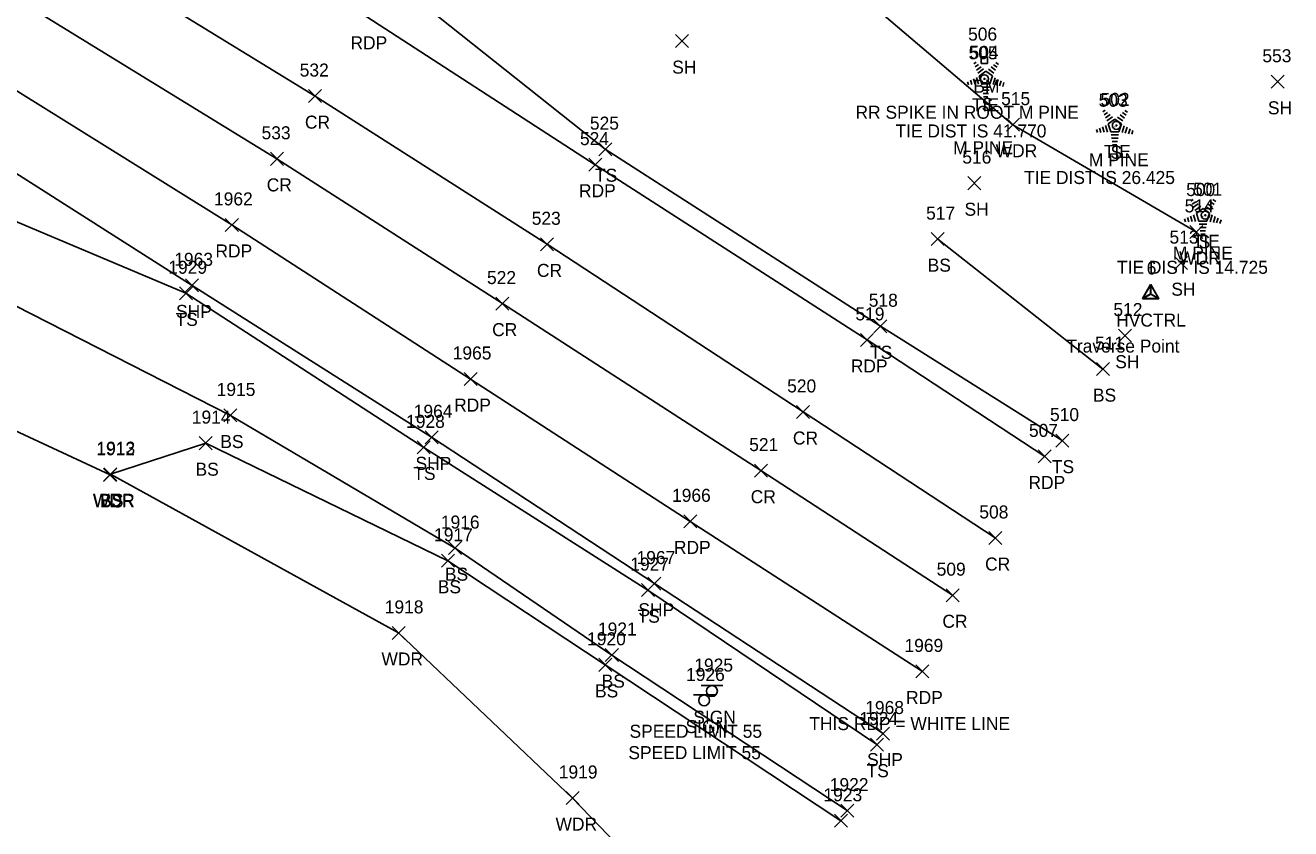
# Model space of a CAD drawing. Extents: x 1629176 to 1637209, y 606063 to 610167.
# Drawn here: x 1630613 to 1630807.4, y 606523.7 to 606647 of the extents above; entities that cross this region are included whole.
import ezdxf

# ---------------------------------------------------------------- set-up
doc = ezdxf.new("R2010")
doc.units = 0
for name, color, linetype in [('C_A', 7, 'Continuous'), ('C_C', 7, 'Continuous'), ('C_I', 7, 'Continuous'), ('CBP', 7, 'Continuous'), ('CPBM', 7, 'Continuous'), ('CPSM', 7, 'Continuous'), ('L_A', 7, 'Continuous'), ('L_C', 7, 'Continuous'), ('L_I', 7, 'Continuous'), ('L_TIC', 7, 'Continuous'), ('LAWA', 7, 'Continuous'), ('LELB', 7, 'Continuous'), ('LTC', 7, 'Continuous'), ('P_A', 7, 'Continuous'), ('P_C', 7, 'Continuous'), ('P_I', 7, 'Continuous'), ('P_TIC', 7, 'Continuous'), ('PET', 7, 'Continuous'), ('PRC', 7, 'Continuous'), ('PSP', 7, 'Continuous'), ('S_A', 7, 'Continuous'), ('S_C', 7, 'Continuous'), ('S_I', 7, 'Continuous'), ('SSGN', 7, 'Continuous')]:
    doc.layers.add(name, color=color, linetype=linetype)

msp = doc.modelspace()

# ---------------------------------------------------------------- linework, layer by layer
at = {"layer": 'CBP'}
for centre, radius in [((1630760.34, 606638.81), 0.625), ((1630760.34, 606638.81), 0.0833), ((1630780.62, 606631.66), 0.625), ((1630780.62, 606631.66), 0.0833), ((1630794.28, 606617.87), 0.625), ((1630794.28, 606617.87), 0.0833)]:
    msp.add_circle(centre, radius, dxfattribs=at)
at = {"layer": 'CPBM'}
for p, q in [((1630759.82, 606641.18), (1630759.82, 606642.18)), ((1630759.82, 606642.18), (1630760.82, 606642.18)), ((1630760.82, 606641.18), (1630759.82, 606641.18)), ((1630760.33, 606641.68), (1630760.33, 606641.68)), ((1630760.33, 606641.68), (1630760.33, 606641.68)), ((1630760.82, 606642.18), (1630760.82, 606641.18))]:
    msp.add_line(p, q, dxfattribs=at)
at = {"layer": 'CPSM'}
for p, q in [((1630784.62, 606605.06), (1630785.87, 606607.23)), ((1630784.64, 606605.05), (1630785.89, 606607.21)), ((1630787.12, 606605.06), (1630785.87, 606607.23)), ((1630785.87, 606605.78), (1630785.87, 606607.23)), ((1630787.14, 606605.05), (1630785.89, 606607.21)), ((1630785.89, 606605.77), (1630785.89, 606607.21)), ((1630784.62, 606605.06), (1630785.87, 606605.78)), ((1630784.62, 606605.06), (1630787.12, 606605.06)), ((1630784.64, 606605.05), (1630785.89, 606605.77)), ((1630784.64, 606605.05), (1630787.14, 606605.05)), ((1630785.87, 606605.78), (1630785.87, 606605.78)), ((1630785.87, 606605.78), (1630787.12, 606605.06)), ((1630785.89, 606605.77), (1630785.89, 606605.77)), ((1630785.89, 606605.77), (1630787.14, 606605.05))]:
    msp.add_line(p, q, dxfattribs=at)
at = {"layer": 'L_TIC'}
for points in [[(1630712.88, 606643.61), (1630714.88, 606645.61)], [(1630714.88, 606643.61), (1630712.88, 606645.61)], [(1630804.42, 606637.36), (1630806.42, 606639.36)], [(1630806.42, 606637.36), (1630804.42, 606639.36)], [(1630763.71, 606630.77), (1630765.71, 606632.77)], [(1630765.71, 606630.77), (1630763.71, 606632.77)], [(1630701.09, 606627.01), (1630703.09, 606629.01)], [(1630703.09, 606627.01), (1630701.09, 606629.01)], [(1630757.79, 606621.79), (1630759.79, 606623.79)], [(1630759.79, 606621.79), (1630757.79, 606623.79)], [(1630791.9, 606614.3), (1630793.9, 606616.3)], [(1630793.9, 606614.3), (1630791.9, 606616.3)], [(1630752.18, 606613.2), (1630754.18, 606615.2)], [(1630754.18, 606613.2), (1630752.18, 606615.2)], [(1630789.57, 606609.51), (1630791.57, 606611.51)], [(1630791.57, 606609.51), (1630789.57, 606611.51)], [(1630636.64, 606604.88), (1630638.64, 606606.88)], [(1630638.64, 606604.88), (1630636.64, 606606.88)], [(1630743.36, 606599.82), (1630745.36, 606601.82)], [(1630745.36, 606599.82), (1630743.36, 606601.82)], [(1630780.96, 606598.38), (1630782.96, 606600.38)], [(1630782.96, 606598.38), (1630780.96, 606600.38)], [(1630777.56, 606593.24), (1630779.56, 606595.24)], [(1630779.56, 606593.24), (1630777.56, 606595.24)], [(1630643.49, 606586.12), (1630645.49, 606588.12)], [(1630645.49, 606586.12), (1630643.49, 606588.12)], [(1630639.68, 606581.87), (1630641.68, 606583.87)], [(1630641.68, 606581.87), (1630639.68, 606583.87)], [(1630673.18, 606581.22), (1630675.18, 606583.22)], [(1630675.18, 606581.22), (1630673.18, 606583.22)], [(1630771.3, 606582.26), (1630773.3, 606584.26)], [(1630773.3, 606582.26), (1630771.3, 606584.26)], [(1630625, 606577), (1630627, 606579)], [(1630627, 606577), (1630625, 606579)], [(1630625, 606577), (1630627, 606579)], [(1630627, 606577), (1630625, 606579)], [(1630625.04, 606577.1), (1630627.04, 606579.1)], [(1630627.04, 606577.1), (1630625.04, 606579.1)], [(1630625.04, 606577.1), (1630627.04, 606579.1)], [(1630627.04, 606577.1), (1630625.04, 606579.1)], [(1630678, 606565.75), (1630680, 606567.75)], [(1630680, 606565.75), (1630678, 606567.75)], [(1630676.91, 606563.81), (1630678.91, 606565.81)], [(1630678.91, 606563.81), (1630676.91, 606565.81)], [(1630707.63, 606559.3), (1630709.63, 606561.3)], [(1630709.63, 606559.3), (1630707.63, 606561.3)], [(1630669.33, 606552.73), (1630671.33, 606554.73)], [(1630671.33, 606552.73), (1630669.33, 606554.73)], [(1630701.07, 606547.83), (1630703.07, 606549.83)], [(1630703.07, 606547.83), (1630701.07, 606549.83)], [(1630702.09, 606549.33), (1630704.09, 606551.33)], [(1630704.09, 606549.33), (1630702.09, 606551.33)], [(1630742.82, 606535.58), (1630744.82, 606537.58)], [(1630744.82, 606535.58), (1630742.82, 606537.58)], [(1630696.07, 606527.38), (1630698.07, 606529.38)], [(1630698.07, 606527.38), (1630696.07, 606529.38)], [(1630738.27, 606525.44), (1630740.27, 606527.44)], [(1630740.27, 606525.44), (1630738.27, 606527.44)], [(1630737.3, 606523.88), (1630739.3, 606525.88)], [(1630739.3, 606523.88), (1630737.3, 606525.88)]]:
    msp.add_lwpolyline(points, dxfattribs=at)
at = {"layer": 'LAWA'}
for points in [[(1630792.9, 606615.3), (1630764.71, 606631.77), (1630727.23, 606663.62), (1630696.05, 606688.29), (1630643.61, 606720.78), (1630609.4, 606762.16), (1630595.94, 606778.67), (1630581.31, 606798.55), (1630556.61, 606821.27), (1630561.53, 606852.75)], [(1630297.68, 606682.91), (1630335.71, 606675.48), (1630386.4, 606666.36), (1630422.65, 606653.68), (1630444.38, 606639.08), (1630446.66, 606637.81), (1630486.16, 606613.28), (1630514.89, 606608.05), (1630539.89, 606609.62), (1630562.09, 606603.08), (1630591.48, 606594.03), (1630626, 606578), (1630626.04, 606578.1), (1630670.33, 606553.73), (1630697.07, 606528.38), (1630722.88, 606501.58)]]:
    msp.add_lwpolyline(points, dxfattribs=at)
at = {"layer": 'LELB'}
for points in [[(1630772.3, 606583.26), (1630744.36, 606600.82), (1630702.09, 606628.01), (1630669.73, 606653.69), (1630639.16, 606677.6), (1630625.62, 606682.65), (1630575.5, 606708.79), (1630543.73, 606726.11), (1630517.88, 606742.14), (1630478.23, 606762.96), (1630430.43, 606788.65), (1630392.8, 606806.98), (1630357.66, 606823.31), (1630317.9, 606842.29), (1630273.51, 606862.27), (1630239.69, 606876.29), (1630209.67, 606888.82), (1630166.54, 606905.65), (1630125.1, 606921.22), (1630084.2, 606935.53), (1630049.16, 606947.36)], [(1630743.82, 606536.58), (1630708.63, 606560.3), (1630674.18, 606582.22), (1630637.64, 606605.88), (1630594.34, 606624.1), (1630571.59, 606644.34), (1630541.22, 606663.48), (1630507.65, 606682.45), (1630477.7, 606699.4), (1630450.89, 606713.6)], [(1630469.72, 606651.64), (1630496.75, 606635.89), (1630520.54, 606626.59), (1630540.08, 606622.19), (1630567.61, 606620.59), (1630601.15, 606609.16), (1630644.49, 606587.12), (1630679, 606566.75), (1630703.09, 606550.33), (1630739.27, 606526.44)], [(1630778.56, 606594.24), (1630753.18, 606614.2)], [(1630626.04, 606578.1), (1630640.68, 606582.87), (1630677.91, 606564.81), (1630702.07, 606548.83), (1630738.3, 606524.88)]]:
    msp.add_lwpolyline(points, dxfattribs=at)
at = {"layer": 'LTC'}
for p, q in [((1630758.7, 606641.09), (1630759.05, 606641.35)), ((1630762.1, 606641.33), (1630762.52, 606641.03)), ((1630758.91, 606640.63), (1630759.44, 606641.01)), ((1630759.12, 606640.16), (1630759.82, 606640.67)), ((1630759.33, 606639.7), (1630760.21, 606640.33)), ((1630759.55, 606639.24), (1630760.56, 606639.97)), ((1630759.55, 606639.24), (1630759.94, 606638.05)), ((1630760.56, 606639.97), (1630761.56, 606639.25)), ((1630760.98, 606640.29), (1630761.79, 606639.7)), ((1630761.56, 606639.25), (1630761.17, 606638.05)), ((1630761.36, 606640.64), (1630762.03, 606640.14)), ((1630761.73, 606640.98), (1630762.28, 606640.59)), ((1630757.73, 606638.37), (1630757.88, 606637.9)), ((1630758.19, 606638.59), (1630758.4, 606637.94)), ((1630758.64, 606638.8), (1630758.91, 606637.97)), ((1630759.1, 606639.02), (1630759.43, 606638)), ((1630761.17, 606638.05), (1630759.94, 606638.05)), ((1630761.13, 606637.55), (1630759.99, 606637.55)), ((1630762, 606638.98), (1630761.66, 606637.94)), ((1630762.44, 606638.73), (1630762.16, 606637.84)), ((1630762.89, 606638.48), (1630762.65, 606637.75)), ((1630763.33, 606638.23), (1630763.15, 606637.65)), ((1630761.05, 606637.05), (1630760.06, 606637.05)), ((1630760.96, 606636.55), (1630760.13, 606636.55)), ((1630760.88, 606636.05), (1630760.21, 606636.05)), ((1630778.53, 606633.73), (1630778.88, 606633.99)), ((1630778.74, 606633.27), (1630779.27, 606633.65)), ((1630778.95, 606632.8), (1630779.65, 606633.31)), ((1630781.19, 606633.28), (1630781.86, 606632.78)), ((1630781.56, 606633.63), (1630782.11, 606633.23)), ((1630781.93, 606633.97), (1630782.35, 606633.67)), ((1630778.47, 606631.45), (1630778.74, 606630.61)), ((1630778.93, 606631.66), (1630779.26, 606630.64)), ((1630779.16, 606632.34), (1630780.04, 606632.97)), ((1630779.38, 606631.88), (1630780.39, 606632.62)), ((1630779.38, 606631.88), (1630779.77, 606630.69)), ((1630780.39, 606632.62), (1630781.39, 606631.89)), ((1630780.81, 606632.93), (1630781.62, 606632.34)), ((1630781.39, 606631.89), (1630781, 606630.69)), ((1630781.83, 606631.62), (1630781.49, 606630.58)), ((1630782.27, 606631.37), (1630781.99, 606630.49)), ((1630777.56, 606631.01), (1630777.71, 606630.55)), ((1630778.02, 606631.23), (1630778.23, 606630.58)), ((1630781, 606630.69), (1630779.77, 606630.69)), ((1630780.96, 606630.19), (1630779.82, 606630.19)), ((1630780.88, 606629.69), (1630779.89, 606629.69)), ((1630782.72, 606631.12), (1630782.48, 606630.39)), ((1630783.16, 606630.87), (1630782.98, 606630.3)), ((1630780.79, 606629.19), (1630779.96, 606629.19)), ((1630780.71, 606628.69), (1630780.04, 606628.69)), ((1630792.06, 606620.02), (1630792.42, 606620.28)), ((1630792.27, 606619.56), (1630792.8, 606619.94)), ((1630795.09, 606619.91), (1630795.64, 606619.51)), ((1630795.46, 606620.26), (1630795.88, 606619.96)), ((1630792.01, 606617.73), (1630792.28, 606616.9)), ((1630792.46, 606617.95), (1630792.79, 606616.93)), ((1630792.48, 606619.09), (1630793.19, 606619.6)), ((1630792.69, 606618.62), (1630793.57, 606619.26)), ((1630792.92, 606618.17), (1630793.93, 606618.9)), ((1630792.92, 606618.17), (1630793.3, 606616.98)), ((1630793.93, 606618.9), (1630794.93, 606618.18)), ((1630794.35, 606619.22), (1630795.16, 606618.63)), ((1630794.93, 606618.18), (1630794.53, 606616.98)), ((1630794.72, 606619.57), (1630795.4, 606619.07)), ((1630795.36, 606617.91), (1630795.02, 606616.87)), ((1630791.1, 606617.3), (1630791.25, 606616.83)), ((1630791.55, 606617.52), (1630791.76, 606616.87)), ((1630794.53, 606616.98), (1630793.3, 606616.98)), ((1630794.5, 606616.48), (1630793.35, 606616.48)), ((1630794.41, 606615.98), (1630793.42, 606615.98)), ((1630795.81, 606617.66), (1630795.52, 606616.77)), ((1630796.25, 606617.41), (1630796.01, 606616.68)), ((1630796.7, 606617.16), (1630796.51, 606616.58)), ((1630794.33, 606615.48), (1630793.5, 606615.48)), ((1630794.24, 606614.98), (1630793.57, 606614.98))]:
    msp.add_line(p, q, dxfattribs=at)
at = {"layer": 'P_TIC'}
for points in [[(1630656.5, 606635.16), (1630658.5, 606637.16)], [(1630658.5, 606635.16), (1630656.5, 606637.16)], [(1630650.63, 606625.53), (1630652.63, 606627.53)], [(1630652.63, 606625.53), (1630650.63, 606627.53)], [(1630699.55, 606624.63), (1630701.55, 606626.63)], [(1630701.55, 606624.63), (1630699.55, 606626.63)], [(1630643.7, 606615.38), (1630645.7, 606617.38)], [(1630645.7, 606615.38), (1630643.7, 606617.38)], [(1630692.14, 606612.4), (1630694.14, 606614.4)], [(1630694.14, 606612.4), (1630692.14, 606614.4)], [(1630637.6, 606606.1), (1630639.6, 606608.1)], [(1630639.6, 606606.1), (1630637.6, 606608.1)], [(1630685.27, 606603.3), (1630687.27, 606605.3)], [(1630687.27, 606603.3), (1630685.27, 606605.3)], [(1630741.32, 606597.72), (1630743.32, 606599.72)], [(1630743.32, 606597.72), (1630741.32, 606599.72)], [(1630680.38, 606591.72), (1630682.38, 606593.72)], [(1630682.38, 606591.72), (1630680.38, 606593.72)], [(1630731.48, 606586.66), (1630733.48, 606588.66)], [(1630733.48, 606586.66), (1630731.48, 606588.66)], [(1630674.39, 606582.77), (1630676.39, 606584.77)], [(1630676.39, 606582.77), (1630674.39, 606584.77)], [(1630768.62, 606579.83), (1630770.62, 606581.83)], [(1630770.62, 606579.83), (1630768.62, 606581.83)], [(1630725, 606577.65), (1630727, 606579.65)], [(1630727, 606577.65), (1630725, 606579.65)], [(1630714.14, 606569.86), (1630716.14, 606571.86)], [(1630716.14, 606569.86), (1630714.14, 606571.86)], [(1630761, 606567.31), (1630763, 606569.31)], [(1630763, 606567.31), (1630761, 606569.31)], [(1630708.63, 606560.3), (1630710.63, 606562.3)], [(1630710.63, 606560.3), (1630708.63, 606562.3)], [(1630754.45, 606558.52), (1630756.45, 606560.52)], [(1630756.45, 606558.52), (1630754.45, 606560.52)], [(1630749.81, 606546.81), (1630751.81, 606548.81)], [(1630751.81, 606546.81), (1630749.81, 606548.81)], [(1630743.78, 606537.28), (1630745.78, 606539.28)], [(1630745.78, 606537.28), (1630743.78, 606539.28)]]:
    msp.add_lwpolyline(points, dxfattribs=at)
at = {"layer": 'PET'}
for points in [[(1630769.62, 606580.83), (1630742.32, 606598.72), (1630700.55, 606625.63), (1630665.45, 606648.34), (1630621.98, 606674.98), (1630606.18, 606684.39), (1630572.37, 606704.1), (1630541.12, 606722.17), (1630498.96, 606745.43), (1630457.51, 606767.81), (1630420.78, 606786.67), (1630374.62, 606809.25), (1630335.12, 606827.65), (1630289.38, 606848.42), (1630250.13, 606865.31), (1630203.69, 606884.49), (1630159.86, 606901.83), (1630115.59, 606918.47), (1630070.26, 606934.37)], [(1630050.76, 606901.68), (1630096.23, 606885.67), (1630143.35, 606868.08), (1630186.15, 606851.44), (1630235.05, 606831.31), (1630271.1, 606815.81), (1630310.69, 606798.07), (1630353.79, 606777.93), (1630392.73, 606758.86), (1630432.29, 606738.62), (1630464.02, 606722.09), (1630502.44, 606701.07), (1630537.98, 606680.83), (1630570.03, 606662.27), (1630609.11, 606638.58), (1630644.7, 606616.38), (1630681.38, 606592.72), (1630715.14, 606570.86), (1630750.81, 606547.81)]]:
    msp.add_lwpolyline(points, dxfattribs=at)
at = {"layer": 'PRC'}
for points in [[(1630762, 606568.31), (1630732.48, 606587.66), (1630693.14, 606613.4), (1630657.5, 606636.16), (1630615.44, 606661.97), (1630565.18, 606692.12), (1630533.4, 606710.56), (1630491.42, 606733.47), (1630450.45, 606755.19), (1630412.78, 606774.87), (1630369.5, 606796.13), (1630328.6, 606815.23), (1630283.03, 606835.75), (1630244.34, 606852.21), (1630197.18, 606871.73), (1630154.28, 606888.46), (1630110.18, 606905.77), (1630065.36, 606921.68)], [(1630755.45, 606559.52), (1630726, 606578.65), (1630686.27, 606604.3), (1630651.63, 606626.53), (1630610.5, 606651.79), (1630559.24, 606682.64), (1630527.45, 606700.94), (1630485.76, 606723.98), (1630445.96, 606745.41), (1630407.11, 606765.59), (1630364.16, 606786.66), (1630323.37, 606805.55), (1630278.9, 606825.47), (1630240.3, 606842.26), (1630192.63, 606861.5), (1630149.2, 606878.91), (1630105.99, 606894.95), (1630061.18, 606910.94)]]:
    msp.add_lwpolyline(points, dxfattribs=at)
at = {"layer": 'PSP'}
msp.add_lwpolyline([(1630045.28, 606892.75), (1630092.08, 606875.64), (1630138.49, 606858.75), (1630183.19, 606841.37), (1630230, 606822.13), (1630266.88, 606805.89), (1630306.04, 606788.47), (1630348.79, 606768.34), (1630387.17, 606749.74), (1630427.91, 606728.87), (1630457.64, 606713.36), (1630497.17, 606691.94), (1630531.87, 606672.45), (1630564.31, 606653.82), (1630602.72, 606629.92), (1630638.6, 606607.1), (1630675.39, 606583.77), (1630709.63, 606561.3), (1630744.78, 606538.28)], dxfattribs=at)
at = {"layer": 'SSGN'}
for p, q in [((1630715.63, 606544.2), (1630718.96, 606544.2)), ((1630716.83, 606545.65), (1630720.16, 606545.65)), ((1630718.47, 606544.81), (1630718.47, 606544.81)), ((1630717.27, 606543.37), (1630717.27, 606543.37))]:
    msp.add_line(p, q, dxfattribs=at)
for centre in [(1630717.27, 606543.37), (1630718.47, 606544.81)]:
    msp.add_circle(centre, 0.833, dxfattribs=at)

# ---------------------------------------------------------------- texts
at = {"layer": 'C_A'}
for s, p in [('BM', (1630758.64, 606636.68)), ('TIE', (1630758.42, 606633.81)), ('TIE', (1630778.69, 606626.66)), ('TIE', (1630792.36, 606612.87)), ('HVCTRL', (1630780.58, 606600.77))]:
    msp.add_text(s, height=2, dxfattribs=at).set_placement(p)
at = {"layer": 'C_C'}
for s, p in [('RR SPIKE IN ROOT M PINE', (1630740.53, 606632.68)), ('TIE DIST IS 41.770', (1630746.68, 606629.81)), ('TIE DIST IS 26.425', (1630766.43, 606622.66)), ('TIE DIST IS 14.725', (1630780.71, 606608.87)), ('Traverse Point', (1630772.92, 606596.78))]:
    msp.add_text(s, height=2, dxfattribs=at).set_placement(p)
at = {"layer": 'C_I'}
for s, p in [('506', (1630757.83, 606644.68)), ('505', (1630757.9, 606641.81)), ('502', (1630778.18, 606634.66)), ('501', (1630792.41, 606620.87)), ('6', (1630785.27, 606608.77))]:
    msp.add_text(s, height=2, dxfattribs=at).set_placement(p)
at = {"layer": 'L_A'}
for s, p in [('SH', (1630712.37, 606639.61)), ('S', (1630759.89, 606633.88)), ('SH', (1630803.9, 606633.36)), ('WDR', (1630762.07, 606626.77)), ('S', (1630779.72, 606626.53)), ('TS', (1630700.5, 606623.01)), ('SH', (1630757.28, 606617.79)), ('S', (1630793.25, 606612.81)), ('WDR', (1630790.26, 606610.3)), ('BS', (1630751.62, 606609.2)), ('SH', (1630789.06, 606605.51)), ('TS', (1630636.05, 606600.88)), ('TS', (1630742.77, 606595.82)), ('SH', (1630780.44, 606594.38)), ('BS', (1630777.01, 606589.24)), ('BS', (1630642.93, 606582.12)), ('BS', (1630639.12, 606577.87)), ('TS', (1630672.59, 606577.22)), ('TS', (1630770.71, 606578.26)), ('WDR', (1630623.36, 606573)), ('WDR', (1630623.4, 606573.1)), ('BS', (1630624.44, 606573)), ('BS', (1630624.48, 606573.1)), ('BS', (1630677.44, 606561.75)), ('BS', (1630676.35, 606559.81)), ('TS', (1630707.04, 606555.3)), ('WDR', (1630667.69, 606548.73)), ('BS', (1630700.51, 606543.83)), ('BS', (1630701.53, 606545.33)), ('TS', (1630742.23, 606531.58)), ('WDR', (1630694.44, 606523.38))]:
    msp.add_text(s, height=2, dxfattribs=at).set_placement(p)
at = {"layer": 'L_C'}
for p in [(1630755.53, 606627.23), (1630776.38, 606625.39), (1630789.3, 606611.06)]:
    msp.add_text('M PINE', height=2, dxfattribs=at).set_placement(p)
at = {"layer": 'L_I'}
for s, p in [('504', (1630758.06, 606641.88)), ('553', (1630803.05, 606641.36)), ('515', (1630762.91, 606634.77)), ('503', (1630777.89, 606634.53)), ('525', (1630699.72, 606631.01)), ('516', (1630756.94, 606625.79)), ('500', (1630791.34, 606620.81)), ('514', (1630791.11, 606618.3)), ('517', (1630751.38, 606617.2)), ('513', (1630788.78, 606613.51)), ('1929', (1630634.94, 606608.88)), ('518', (1630742.57, 606603.82)), ('512', (1630780.16, 606602.38)), ('511', (1630777.34, 606597.24)), ('1915', (1630642.37, 606590.12)), ('1914', (1630638.55, 606585.87)), ('1928', (1630671.48, 606585.22)), ('510', (1630770.42, 606586.26)), ('1912', (1630623.87, 606581)), ('1912', (1630623.87, 606581)), ('1913', (1630623.91, 606581.1)), ('1913', (1630623.91, 606581.1)), ('1916', (1630676.82, 606569.75)), ('1917', (1630675.78, 606567.81)), ('1927', (1630705.93, 606563.3)), ('1918', (1630668.2, 606556.73)), ('1920', (1630699.29, 606551.83)), ('1921', (1630700.96, 606553.33)), ('1924', (1630741.12, 606539.58)), ('1919', (1630694.94, 606531.38)), ('1922', (1630736.58, 606529.44)), ('1923', (1630735.61, 606527.88))]:
    msp.add_text(s, height=2, dxfattribs=at).set_placement(p)
at = {"layer": 'LTC'}
for p in [(1630760.45, 606638.99), (1630780.28, 606631.63), (1630793.81, 606617.92)]:
    msp.add_text('.', height=1.04, rotation=270, dxfattribs=at).set_placement(p)
at = {"layer": 'P_A'}
for s, p in [('RDP', (1630662.93, 606643.34)), ('CR', (1630655.93, 606631.16)), ('CR', (1630650.06, 606621.53)), ('RDP', (1630698.04, 606620.63)), ('RDP', (1630642.18, 606611.38)), ('CR', (1630691.58, 606608.4)), ('SHP', (1630636.13, 606602.1)), ('CR', (1630684.7, 606599.3)), ('RDP', (1630739.81, 606593.72)), ('RDP', (1630678.86, 606587.72)), ('CR', (1630730.91, 606582.66)), ('SHP', (1630672.92, 606578.77)), ('RDP', (1630767.11, 606575.83)), ('CR', (1630724.43, 606573.65)), ('RDP', (1630712.63, 606565.86)), ('CR', (1630760.44, 606563.31)), ('SHP', (1630707.17, 606556.3)), ('CR', (1630753.88, 606554.52)), ('RDP', (1630748.3, 606542.81)), ('SHP', (1630742.31, 606533.28))]:
    msp.add_text(s, height=2, dxfattribs=at).set_placement(p)
at = {"layer": 'P_C'}
msp.add_text('THIS RDP = WHITE LINE', height=2, dxfattribs=at).set_placement((1630733.44, 606538.81))
at = {"layer": 'P_I'}
for s, p in [('532', (1630655.13, 606639.16)), ('533', (1630649.27, 606629.53)), ('524', (1630698.19, 606628.63)), ('1962', (1630641.96, 606619.38)), ('523', (1630690.78, 606616.4)), ('1963', (1630635.86, 606610.1)), ('522', (1630683.91, 606607.3)), ('519', (1630740.52, 606601.72)), ('1965', (1630678.64, 606595.72)), ('520', (1630730.03, 606590.66)), ('1964', (1630672.65, 606586.77)), ('507', (1630767.18, 606583.83)), ('521', (1630724.2, 606581.65)), ('1966', (1630712.34, 606573.86)), ('508', (1630759.56, 606571.31)), ('1967', (1630706.89, 606564.3)), ('509', (1630753, 606562.52)), ('1969', (1630748.06, 606550.81)), ('1968', (1630742.03, 606541.28))]:
    msp.add_text(s, height=2, dxfattribs=at).set_placement(p)
at = {"layer": 'S_A'}
for p in [(1630714.41, 606538.35), (1630715.61, 606539.79)]:
    msp.add_text('SIGN', height=2, dxfattribs=at).set_placement(p)
at = {"layer": 'S_C'}
for p in [(1630705.81, 606537.63), (1630705.63, 606534.35)]:
    msp.add_text('SPEED LIMIT 55', height=2, dxfattribs=at).set_placement(p)
at = {"layer": 'S_I'}
for s, p in [('1925', (1630715.76, 606547.79)), ('1926', (1630714.5, 606546.35))]:
    msp.add_text(s, height=2, dxfattribs=at).set_placement(p)

doc.saveas('drawing.dxf')
